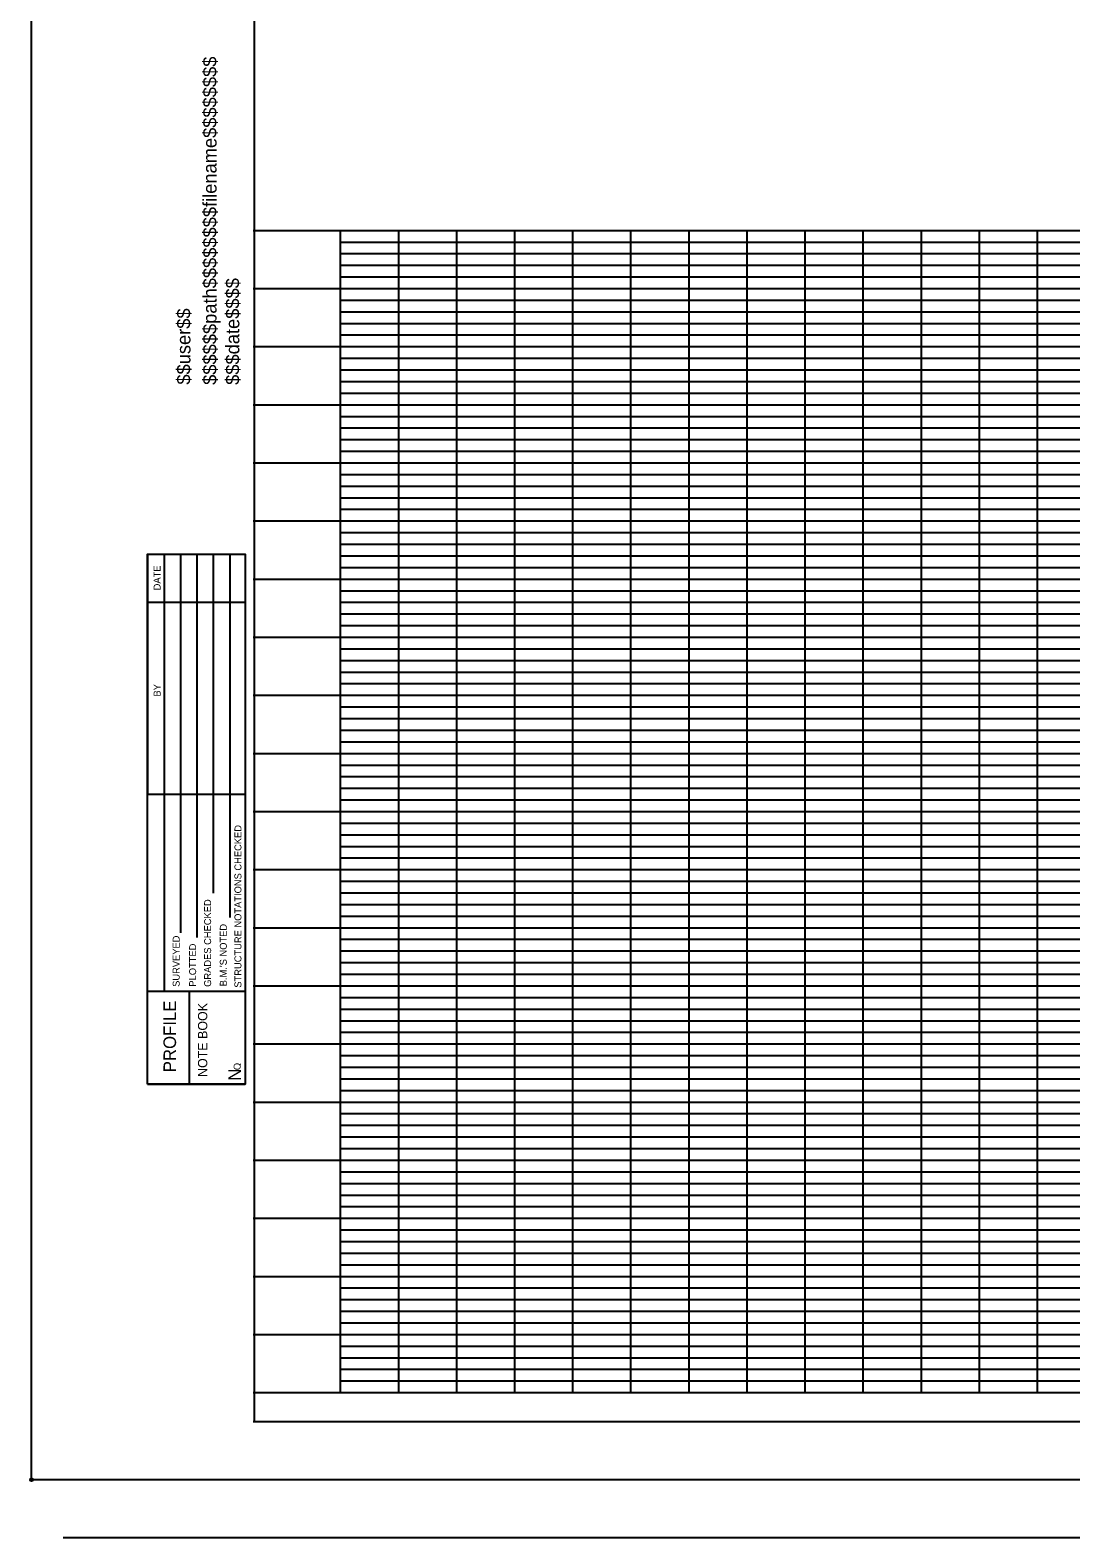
# Model space of a CAD drawing. Extents: x -184 to 1613, y -562 to 587.
# Drawn here: x -184 to 264, y -562 to 86 of the extents above; entities that cross this region are included whole.
import ezdxf

# ---------------------------------------------------------------- set-up
doc = ezdxf.new("R2010")
doc.units = 0
for name, color, linetype in [('Level 1', 7, 'Continuous'), ('Level 2', 7, 'Continuous'), ('Level 3', 7, 'Continuous'), ('Level 50', 7, 'Continuous')]:
    doc.layers.add(name, color=color, linetype=linetype)

msp = doc.modelspace()

# ---------------------------------------------------------------- linework, layer by layer
at = {"layer": 'Level 1'}
for p, q in [((-182.9, -537.5), (-182.9, 562.5)), ((-87, 537.5), (-87, -512.5)), ((-87.5, 0), (1588.35, 0)), ((-50, 0), (-50, -500)), ((-25, 0), (-25, -500)), ((25, 0), (25, -500)), ((75, 0), (75, -500)), ((125, 0), (125, -500)), ((175, 0), (175, -500)), ((225, 0), (225, -500)), ((-49.95, -5), (1549.8, -5)), ((-49.95, -10), (1549.25, -10)), ((-49.95, -15), (1549.8, -15)), ((-49.9, -20), (1549.8, -20)), ((-49.95, -30), (1549.8, -30)), ((-49.95, -35), (1548.75, -35)), ((-49.95, -40), (1549.25, -40)), ((-49.95, -45), (1549.8, -45)), ((-49.95, -55), (1549.8, -55)), ((-49.95, -60), (1549.8, -60)), ((-49.95, -65), (1549.25, -65)), ((-49.95, -70), (1549.8, -70)), ((-49.95, -80), (1548.75, -80)), ((-49.95, -85), (1548.75, -85)), ((-49.95, -90), (1549.25, -90)), ((-49.95, -95), (1549.25, -95)), ((-49.95, -105), (1548.75, -105)), ((-49.95, -110), (1549.25, -110)), ((-49.95, -115), (1548.75, -115)), ((-49.9, -120), (1549.8, -120)), ((-49.95, -130), (1549.25, -130)), ((-49.95, -135), (1549.25, -135)), ((-132.95, -139.3), (-132.95, -242.5)), ((-125.85, -139.3), (-125.85, -327.25)), ((-118.8, -139.3), (-118.8, -302.2)), ((-111.7, -139.3), (-111.7, -304.2)), ((-104.65, -139.3), (-104.65, -285.1)), ((-97.55, -139.3), (-97.55, -295.65)), ((-49.95, -140), (1549.25, -140)), ((-49.95, -145), (1549.25, -145)), ((-49.85, -155), (1548.75, -155)), ((-132.95, -159.95), (-90.95, -159.95)), ((-49.85, -160), (1548.75, -160)), ((-49.9, -165), (1549.25, -165)), ((-49.9, -170), (1549.25, -170)), ((-49.95, -180), (1549.25, -180)), ((-49.95, -185), (1549.25, -185)), ((-49.95, -190), (1548.75, -190)), ((-49.95, -195), (1549.25, -195)), ((-49.95, -195), (1549.25, -195)), ((-49.95, -195), (1548.75, -195)), ((-49.95, -205), (1549.8, -205)), ((-49.95, -210), (1549.8, -210)), ((-49.95, -215), (1549.8, -215)), ((-49.95, -220), (1549.8, -220)), ((-49.95, -230), (1549.8, -230)), ((-49.95, -235), (1549.8, -235)), ((-49.95, -240), (1549.8, -240)), ((-132.95, -242.5), (-90.95, -242.5)), ((-49.95, -245), (1549.8, -245)), ((-49.95, -255), (1549.85, -255)), ((-49.95, -260), (1549.85, -260)), ((-49.95, -265), (1549.85, -265)), ((-49.95, -270), (1549.85, -270)), ((-49.95, -280), (1549.85, -280)), ((-49.95, -285), (1549.85, -285)), ((-49.95, -290), (1549.85, -290)), ((-49.95, -295), (1549.85, -295)), ((-49.95, -305), (1549.85, -305)), ((-49.95, -310), (1549.85, -310)), ((-49.95, -315), (1549.85, -315)), ((-49.95, -320), (1549.85, -320)), ((-132.95, -327.3), (-90.95, -327.3)), ((-132.95, -367.3), (-132.95, -327.3)), ((-114.95, -367.3), (-114.95, -327.3)), ((-49.95, -330), (1549.85, -330)), ((-49.9, -330), (1549.85, -330)), ((-49.95, -335), (1549.85, -335)), ((-49.9, -340), (1549.6, -340)), ((-49.9, -345), (1549.6, -345)), ((-49.9, -355), (1549.8, -355)), ((-49.95, -360), (1549.95, -360)), ((-132.95, -367.3), (-90.95, -367.3)), ((-49.95, -365), (1549.95, -365)), ((-49.9, -370), (1549.95, -370)), ((-49.95, -380), (1549.95, -380)), ((-49.95, -385), (1549.95, -385)), ((-49.95, -390), (1549.95, -390)), ((-49.9, -395), (1549.95, -395)), ((-49.95, -405), (1549.95, -405)), ((-49.95, -410), (1549.95, -410)), ((-49.95, -415), (1549.95, -415)), ((-49.95, -420), (1549.85, -420)), ((-49.9, -430), (1549.6, -430)), ((-49.95, -435), (1549.85, -435)), ((-49.95, -440), (1549.85, -440)), ((-49.95, -445), (1549.85, -445)), ((-49.95, -460), (1549.85, -460)), ((-49.85, -455), (1549.85, -455)), ((-49.95, -465), (1549.85, -465)), ((-49.95, -470), (1549.85, -470)), ((-49.85, -480), (1549.85, -480)), ((-49.85, -485), (1549.85, -485)), ((-49.85, -490), (1549.85, -490)), ((-49.85, -495), (1549.85, -495)), ((-87.5, -500), (1588.35, -500)), ((-87.5, -500), (1588.35, -500)), ((-87.5, -512.5), (1588.35, -512.5)), ((1590.65, -537.5), (-169.35, -537.5)), ((1590.65, -562.5), (-169.35, -562.5))]:
    msp.add_line(p, q, dxfattribs=at)
msp.add_lwpolyline([(-132.95, -367.3), (-132.95, -139.3), (-90.95, -139.3), (-90.95, -367.3)], close=True, dxfattribs=at)
msp.add_circle((-182.9, -537.5), 0.607, dxfattribs=at)
at = {"layer": 'Level 2'}
for p, q in [((-87.5, -25), (1588.35, -25)), ((-87.5, -75), (1588.35, -75)), ((-87.5, -125), (1588.35, -125)), ((-87.5, -175), (1588.35, -175)), ((-87.35, -175), (1588.35, -175)), ((-87.5, -225), (1588.35, -225)), ((-87.5, -275), (1588.35, -275)), ((-87.5, -325), (1588.35, -325)), ((-87.5, -375), (1588.35, -375)), ((-87.5, -425), (1588.35, -425)), ((-87.5, -475), (1588.35, -475))]:
    msp.add_line(p, q, dxfattribs=at)
at = {"layer": 'Level 3'}
for p, q in [((0, 0), (0, -500)), ((50, 0), (50, -500)), ((100, 0), (100, -500)), ((150, 0), (150, -500)), ((200, 0), (200, -500)), ((250, 0), (250, -500)), ((-87.5, -50), (1588.35, -50)), ((-87.5, -100), (1588.35, -100)), ((-87.5, -150), (1588.35, -150)), ((-87.5, -200), (1588.35, -200)), ((-87.5, -250), (1588.35, -250)), ((-87.5, -300), (1588.35, -300)), ((-87.5, -350), (1588.35, -350)), ((-87.5, -400), (1588.35, -400)), ((-87.5, -450), (1588.35, -450))]:
    msp.add_line(p, q, dxfattribs=at)
at = {"layer": 'Level 50'}
msp.add_lwpolyline([(-182.9, 562.5), (1613, 562.5), (1613, -537.5), (-182.9, -537.5)], close=True, dxfattribs=at)

# ---------------------------------------------------------------- texts
at = {"layer": 'Level 1'}
for s, height, p in [('$$$$$$path$$$$$$$$filename$$$$$$$$', 5.88, (-103.25, -66.45)), ('$$$date$$$$', 5.88, (-93.45, -66.45)), ('$$user$$', 5.88, (-114.5, -66.35)), ('DATE', 3, (-127.35, -154.85)), ('BY', 3, (-127.35, -200.55)), ('STRUCTURE NOTATIONS CHECKED', 3, (-92.55, -325.8)), ('GRADES CHECKED', 3, (-105.6, -325.45)), ('SURVEYED', 3, (-119.15, -325.45)), ("B.M.'S NOTED", 3, (-98.85, -325.2)), ('PLOTTED', 3, (-112.05, -325.35)), ('PROFILE', 5.4, (-120.7, -362.2)), ('NOTE BOOK', 4, (-107.25, -364.2)), ('N', 5.4, (-92.8, -365.85)), ('O', 3, (-92.9, -361.3))]:
    msp.add_text(s, height=height, rotation=90, dxfattribs=at).set_placement(p)
msp.add_text('.', height=3, dxfattribs=at).set_placement((-93.55, -358.9))

doc.saveas('drawing.dxf')
